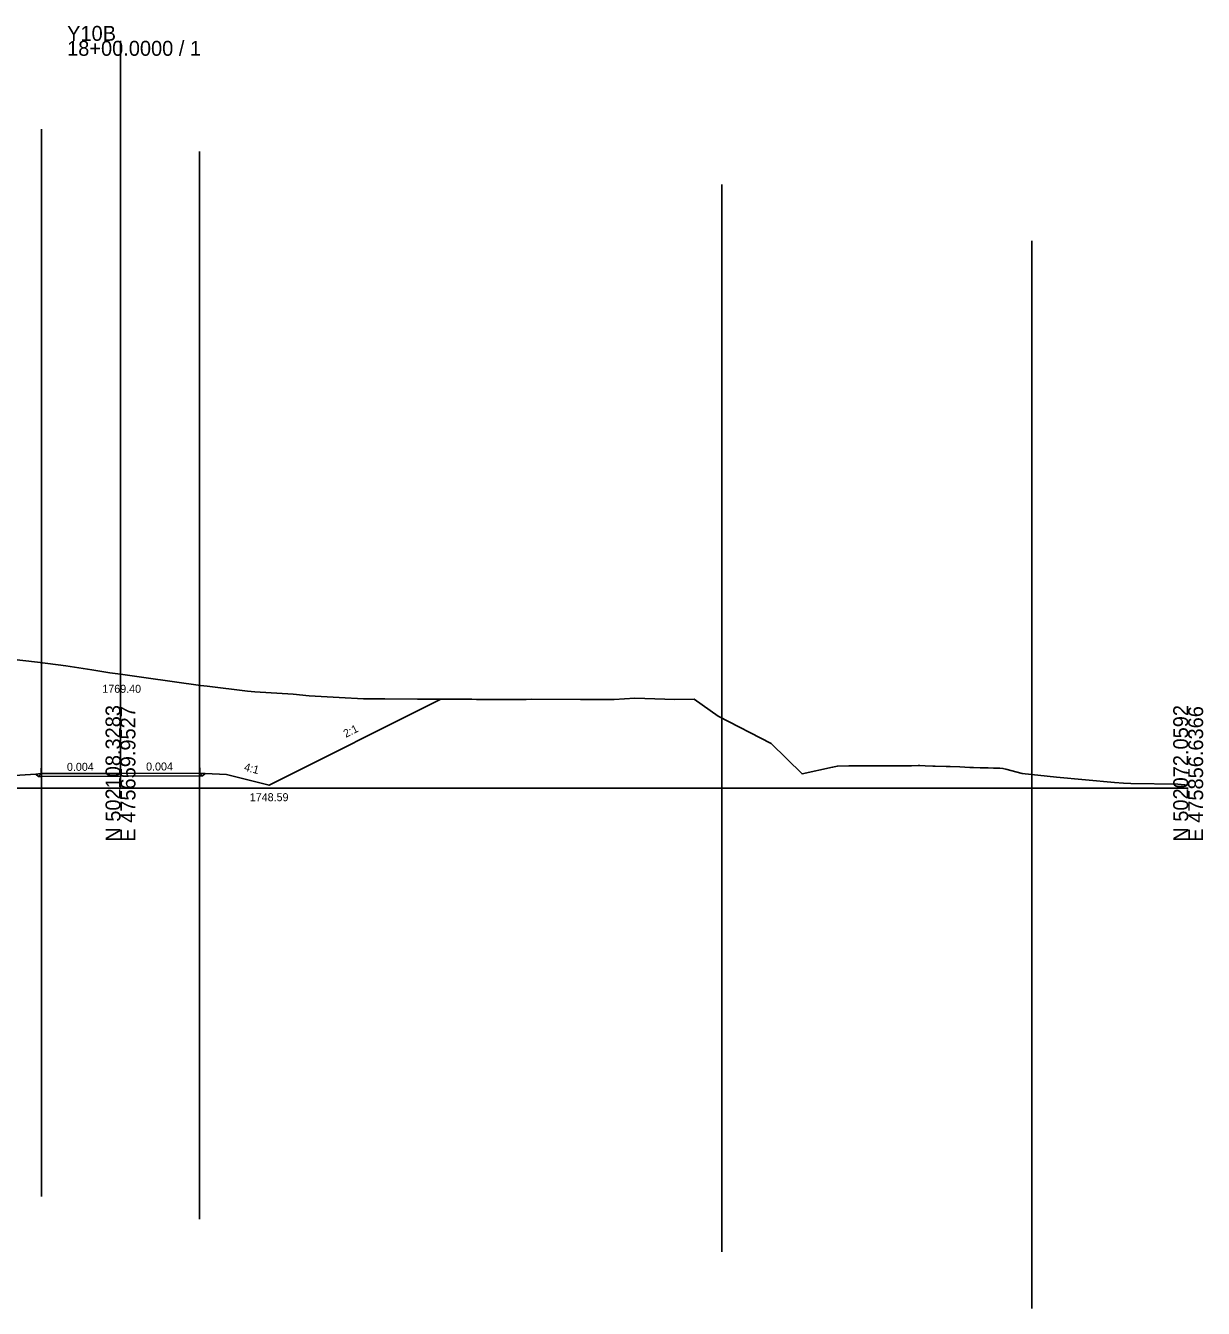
# Model space of a CAD drawing. Extents: x -26 to 1803, y -10 to 9558.
# Drawn here: x 182.2 to 402.8, y 7902.6 to 8142.9 of the extents above; entities that cross this region are included whole.
import ezdxf

# ---------------------------------------------------------------- set-up
doc = ezdxf.new("R2010")
doc.units = 0
for name, color, linetype in [('Exist Cross Section Cell', 7, 'Continuous'), ('Exist XS Center Line Elevation Label', 7, 'Continuous'), ('Exist XS Ground Line', 7, 'Continuous'), ('Prop XS Ditch Slope Text', 7, 'Continuous'), ('Prop XS Ditch Standard Text', 7, 'Continuous'), ('Prop XS Dump Level', 7, 'Continuous'), ('Prop XS Earthwork Shape', 7, 'Continuous'), ('Prop XS EOT Tick Mark', 7, 'Continuous'), ('Prop XS Finish Grade', 7, 'Continuous'), ('Prop XS Finish Grade Earthwork', 7, 'Continuous'), ('Prop XS Finish Grade Pavement', 7, 'Continuous'), ('Prop XS Hydro Typical Ditch Data', 7, 'Continuous'), ('Prop XS Pvmt Edge Slope', 7, 'Continuous'), ('Prop XS SE Text', 7, 'Continuous'), ('Prop XS Shoulder Borrow Shape', 7, 'Continuous'), ('Prop XS Side Slope Text', 7, 'Continuous'), ('Prop XS Subgrade Earthwork', 7, 'Continuous'), ('Scratch_Level_2', 7, 'Continuous')]:
    doc.layers.add(name, color=color, linetype=linetype)

msp = doc.modelspace()

# ---------------------------------------------------------------- linework, layer by layer
at = {"layer": 'Exist Cross Section Cell'}
for p, q in [((200, 8000), (200, 8140.06)), ((0, 8000), (200, 8000)), ((200, 8000), (400, 8000))]:
    msp.add_line(p, q, dxfattribs=at)
at = {"layer": 'Exist XS Ground Line'}
msp.add_lwpolyline([(177.28, 8024.46), (184.47, 8023.62), (189.75, 8022.93), (194.64, 8022.21), (198, 8021.67), (200, 8021.4), (204.81, 8020.73), (214.98, 8019.27), (216.24, 8019.12), (223.76, 8018.22), (225.15, 8018.09), (232.35, 8017.63), (235.32, 8017.36), (240.94, 8016.99), (245.49, 8016.77), (249.52, 8016.76), (255.66, 8016.7), (258.11, 8016.68), (265.83, 8016.68), (266.7, 8016.67), (271.4, 8016.66), (276, 8016.67), (277.04, 8016.68), (286.17, 8016.64), (292.46, 8016.67), (296.34, 8016.87), (303.84, 8016.65), (307.43, 8016.73), (311.93, 8013.52), (321.9, 8008.41), (327.67, 8002.69), (333.39, 8003.95), (334.29, 8004.17), (336.45, 8004.2), (336.91, 8004.2), (337.62, 8004.2), (339.47, 8004.2), (339.79, 8004.2), (341.55, 8004.22), (342.11, 8004.22), (344.55, 8004.23), (346.21, 8004.23), (347.09, 8004.23), (348.18, 8004.24), (349.4, 8004.25), (349.73, 8004.25), (350.73, 8004.22), (352.15, 8004.16), (352.63, 8004.15), (354.69, 8004.08), (355.41, 8004.06), (357.22, 8004), (359.08, 8003.93), (359.77, 8003.91), (361.06, 8003.87), (362.12, 8003.84), (362.51, 8003.83), (363.52, 8003.79), (364.72, 8003.76), (365.31, 8003.73), (365.83, 8003.57), (368.91, 8002.75), (375.32, 8002.09), (386.19, 8001.12), (387.88, 8000.97), (389.27, 8000.93), (398.05, 8000.8), (400, 8000.59)], dxfattribs=at)
at = {"layer": 'Prop XS Dump Level'}
for p, q in [((185.17, 8002.75), (200, 8002.81)), ((200, 8002.81), (214.83, 8002.87))]:
    msp.add_line(p, q, dxfattribs=at)
at = {"layer": 'Prop XS Earthwork Shape'}
msp.add_lwpolyline([(177.28, 8024.46), (184.47, 8023.62), (189.75, 8022.93), (194.64, 8022.21), (198, 8021.67), (200, 8021.4), (204.81, 8020.73), (214.98, 8019.27), (216.24, 8019.12), (223.76, 8018.22), (225.15, 8018.09), (232.35, 8017.63), (235.32, 8017.36), (240.94, 8016.99), (245.49, 8016.77), (249.52, 8016.76), (255.66, 8016.7), (258.11, 8016.68), (260.03, 8016.68), (227.83, 8000.59), (219.83, 8002.59), (215.85, 8002.81), (215.37, 8002.33), (214.83, 8002.33), (200, 8002.27), (185.17, 8002.21), (184.63, 8002.21), (184.15, 8002.68), (180.17, 8002.43)], dxfattribs=at)
at = {"layer": 'Prop XS EOT Tick Mark'}
for p, q in [((185.17, 8002.75), (185.17, 8003.75)), ((214.83, 8002.87), (214.83, 8003.87))]:
    msp.add_line(p, q, dxfattribs=at)
at = {"layer": 'Prop XS Finish Grade'}
for p, q in [((185.17, 8002.75), (184.15, 8002.68)), ((214.83, 8002.87), (215.85, 8002.81))]:
    msp.add_line(p, q, dxfattribs=at)
at = {"layer": 'Prop XS Finish Grade Earthwork'}
for p, q in [((227.83, 8000.59), (260.03, 8016.68)), ((184.15, 8002.68), (180.17, 8002.43)), ((215.85, 8002.81), (219.83, 8002.59)), ((219.83, 8002.59), (227.83, 8000.59))]:
    msp.add_line(p, q, dxfattribs=at)
at = {"layer": 'Prop XS Finish Grade Pavement'}
for p, q in [((185.17, 8002.75), (200, 8002.81)), ((200, 8002.81), (214.83, 8002.87))]:
    msp.add_line(p, q, dxfattribs=at)
at = {"layer": 'Prop XS Hydro Typical Ditch Data'}
for p, q in [((227.83, 8000.59), (260.03, 8016.68)), ((219.83, 8002.59), (227.83, 8000.59))]:
    msp.add_line(p, q, dxfattribs=at)
at = {"layer": 'Prop XS Pvmt Edge Slope'}
for p, q in [((185.17, 8002.75), (184.63, 8002.21)), ((214.83, 8002.87), (215.37, 8002.33))]:
    msp.add_line(p, q, dxfattribs=at)
at = {"layer": 'Prop XS Shoulder Borrow Shape'}
for points in [[(185.17, 8002.75), (184.15, 8002.68), (184.63, 8002.21)], [(214.83, 8002.87), (215.85, 8002.81), (215.37, 8002.33)]]:
    msp.add_lwpolyline(points, close=True, dxfattribs=at)
at = {"layer": 'Prop XS Subgrade Earthwork'}
for p, q in [((184.63, 8002.21), (184.15, 8002.68)), ((185.17, 8002.21), (184.63, 8002.21)), ((200, 8002.27), (185.17, 8002.21)), ((214.83, 8002.33), (200, 8002.27)), ((214.83, 8002.33), (215.37, 8002.33)), ((215.37, 8002.33), (215.85, 8002.81))]:
    msp.add_line(p, q, dxfattribs=at)
at = {"layer": 'Scratch_Level_2'}
for p, q in [((185.18, 8123.53), (185.18, 7923.53)), ((214.82, 8119.3), (214.82, 7919.3)), ((312.66, 8113.15), (312.66, 7913.15)), ((370.74, 8102.56), (370.74, 7902.56))]:
    msp.add_line(p, q, dxfattribs=at)

# ---------------------------------------------------------------- texts
at = {"layer": 'Exist Cross Section Cell'}
for s, p in [('Y10B', (190, 8140.06)), ('18+00.0000 / 1', (190, 8137.26))]:
    msp.add_text(s, height=2.8, dxfattribs=at).set_placement(p)
for s, p in [('N 502108.3283', (200, 7990)), ('E 475659.9527', (202.8, 7990)), ('N 502072.0592', (400, 7990)), ('E 475856.6366', (402.8, 7990))]:
    msp.add_text(s, height=2.8, rotation=90, dxfattribs=at).set_placement(p)
at = {"layer": 'Exist XS Center Line Elevation Label'}
msp.add_text('1769.40', height=1.5, dxfattribs=at).set_placement((196.6, 8017.9))
at = {"layer": 'Prop XS Ditch Slope Text'}
msp.add_text('4:1', height=1.5, rotation=345.9674, dxfattribs=at).set_placement((223.04, 8003.33))
at = {"layer": 'Prop XS Ditch Standard Text'}
msp.add_text('1748.59', height=1.5, dxfattribs=at).set_placement((224.22, 7997.59))
at = {"layer": 'Prop XS Dump Level'}
msp.add_text('Case1', height=0.04, dxfattribs=at).set_placement((219.83, 8002.55))
at = {"layer": 'Prop XS SE Text'}
for p in [(189.97, 8003.27), (204.8, 8003.33)]:
    msp.add_text('0.004', height=1.5, rotation=0.2303, dxfattribs=at).set_placement(p)
at = {"layer": 'Prop XS Side Slope Text'}
msp.add_text('2:1', height=1.5, rotation=26.5589, dxfattribs=at).set_placement((242.2, 8009.45))

doc.saveas('drawing.dxf')
